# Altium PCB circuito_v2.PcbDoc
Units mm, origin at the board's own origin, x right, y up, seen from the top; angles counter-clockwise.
Board outline 77.47 x 60.58 mm, 2 copper layers (Top Layer, Bottom Layer); 47 components, 32 nets, 112 pads, 28 vias.
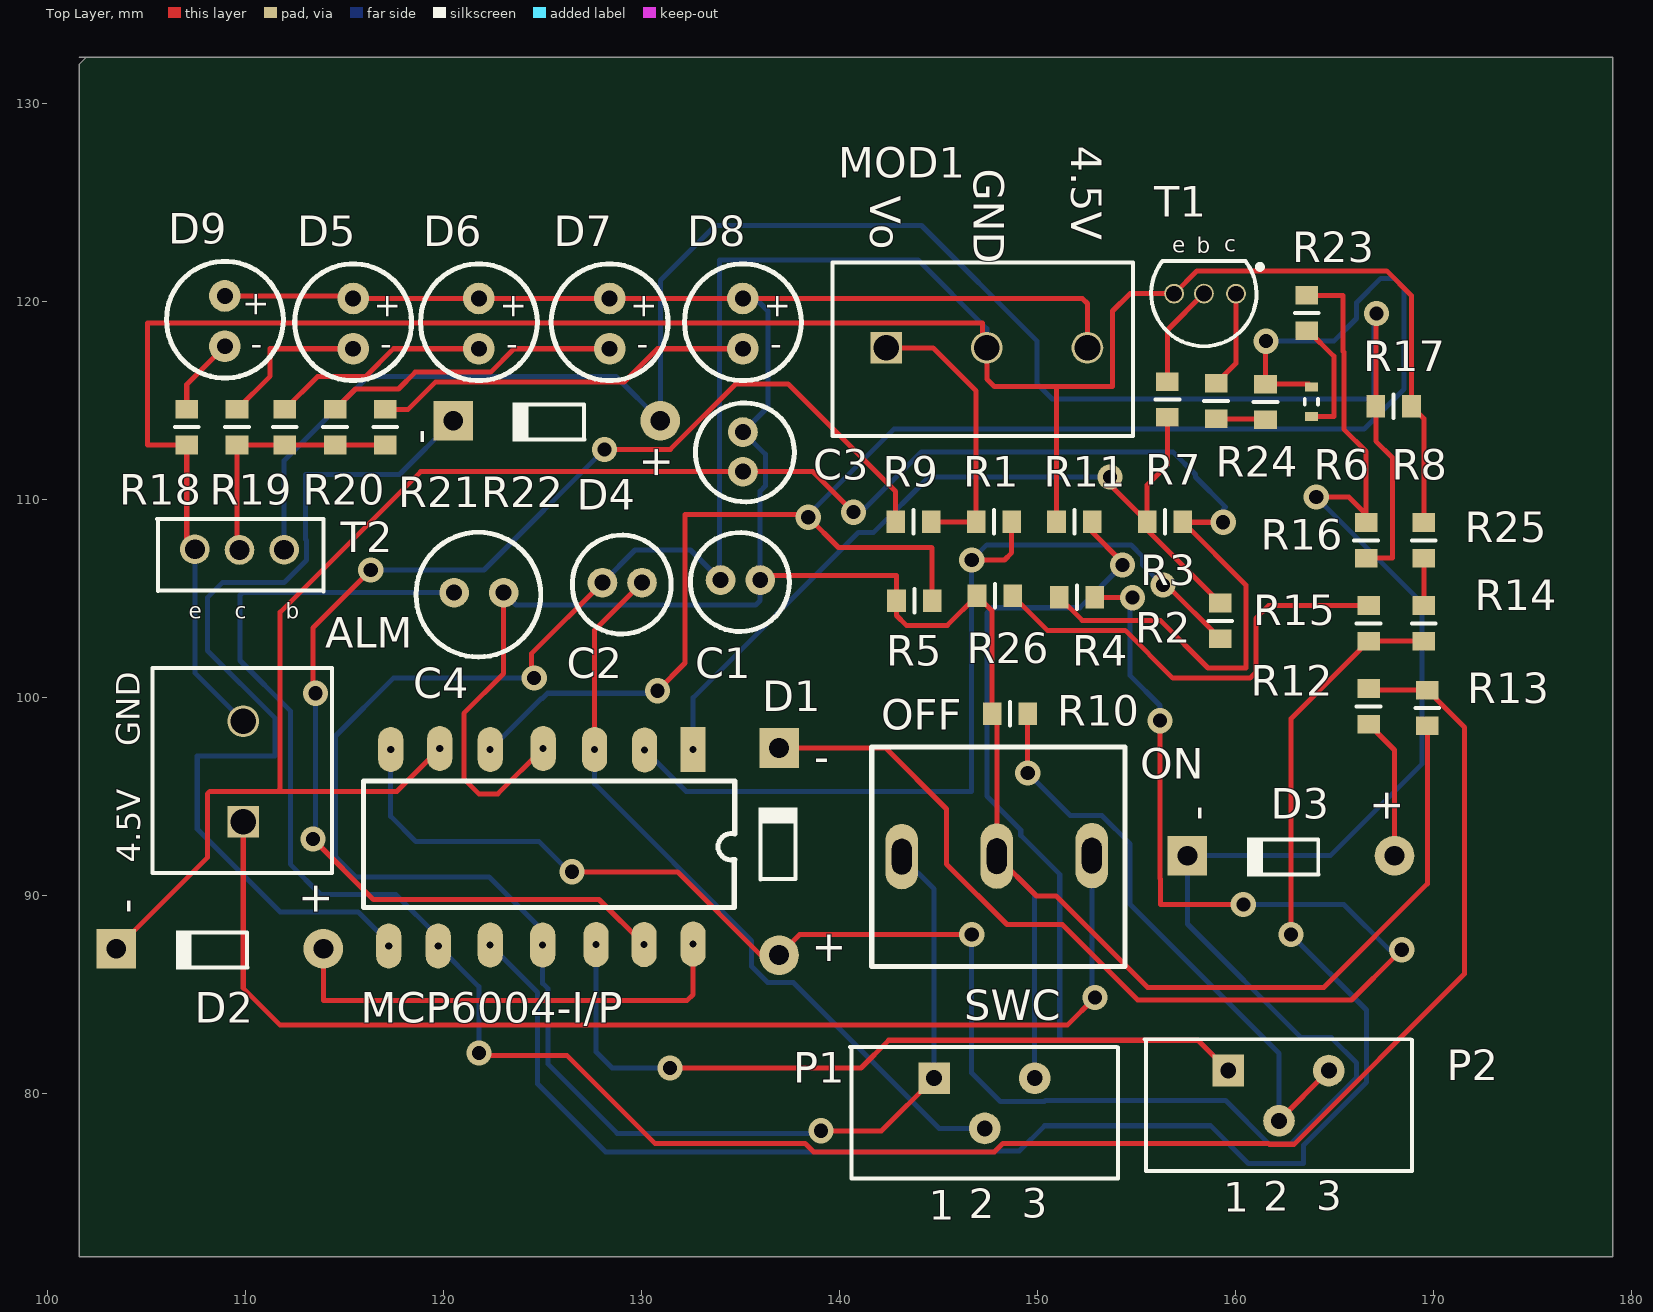
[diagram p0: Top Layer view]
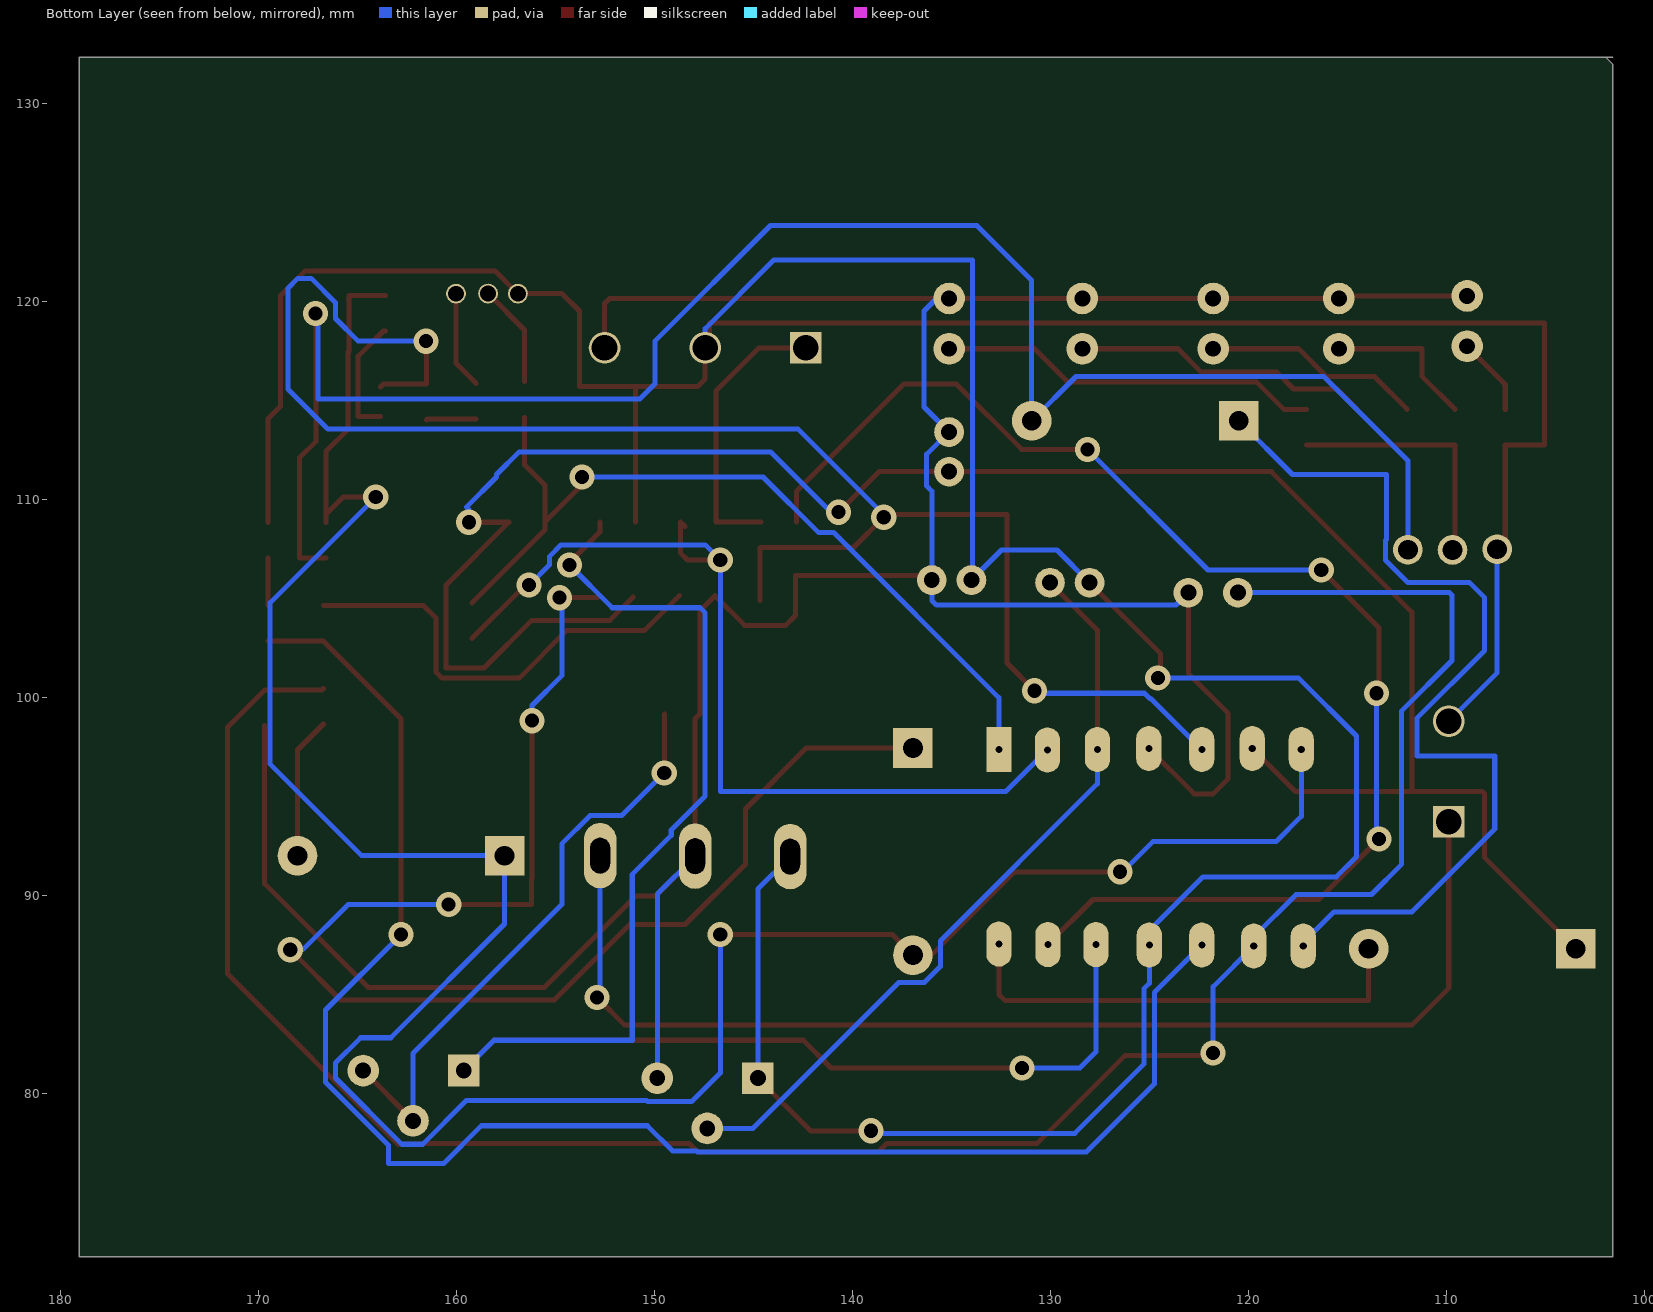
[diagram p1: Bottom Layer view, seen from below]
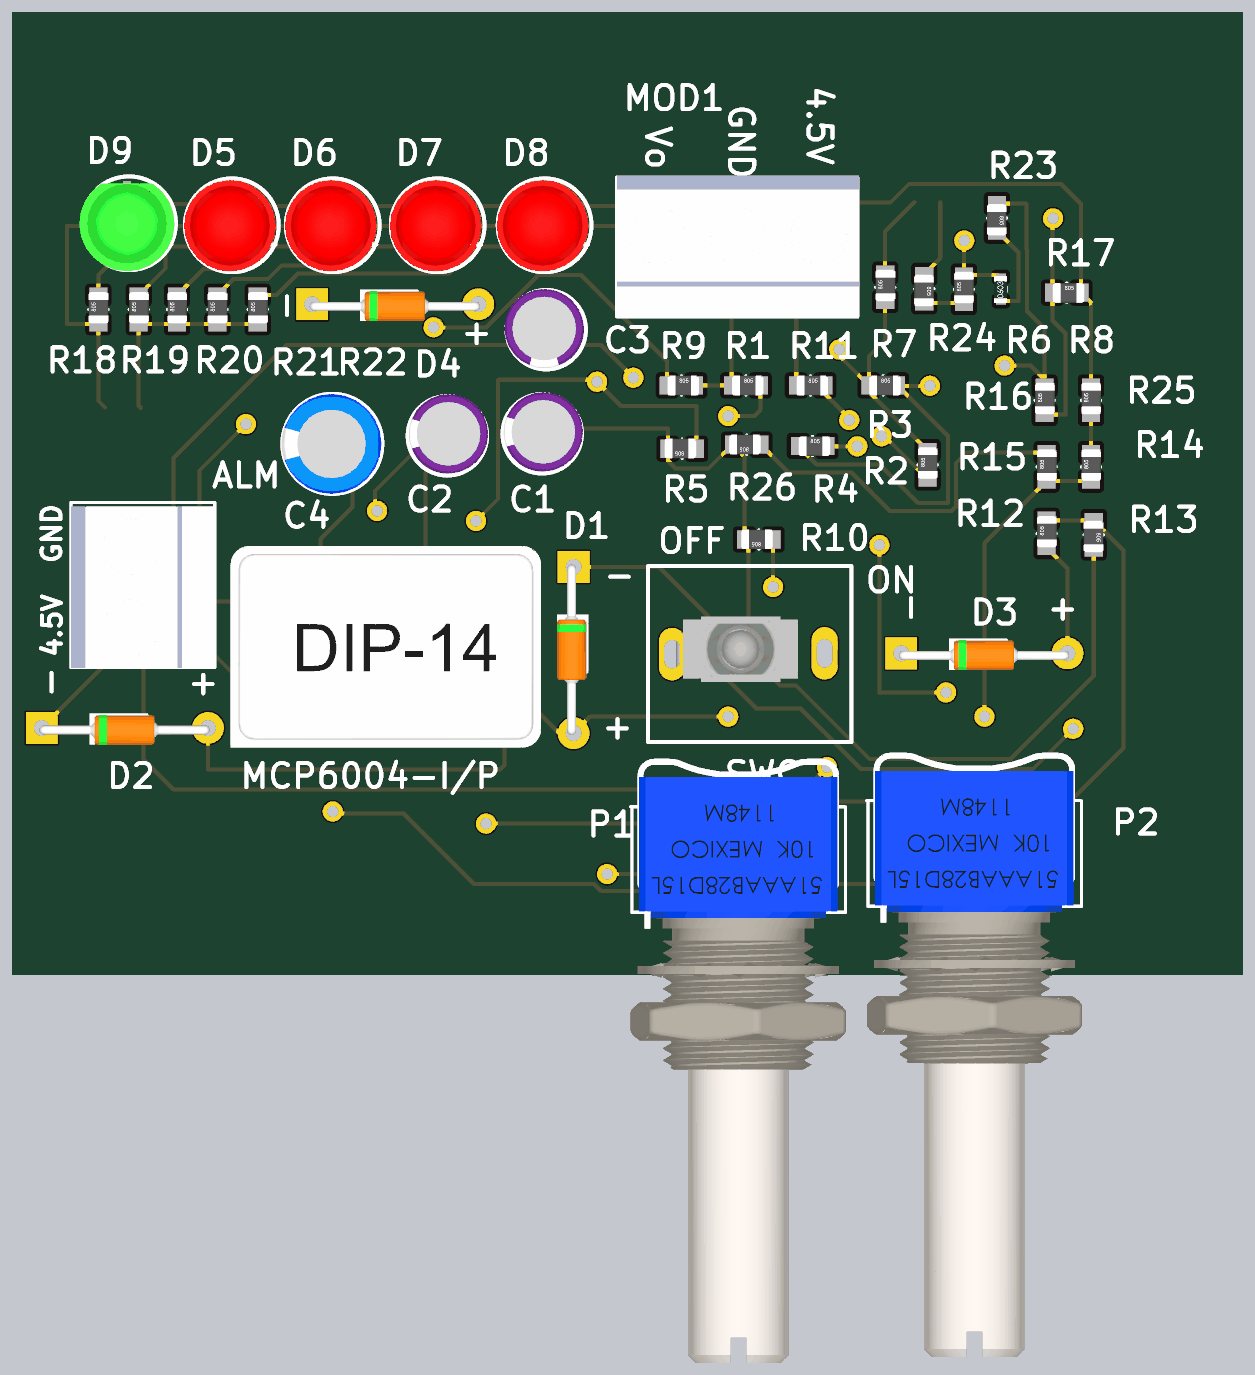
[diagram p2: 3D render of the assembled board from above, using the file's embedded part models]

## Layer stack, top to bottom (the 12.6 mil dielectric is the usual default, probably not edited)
Top Layer: signal copper 0.0356
Dielectric: dielectric 0.32, FR-4, Dk 4.8
Bottom Layer: signal copper 0.0356

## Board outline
101.6,132.334 179.07,132.334 179.07,71.755 101.6,71.755 101.6,131.953 101.981,132.334

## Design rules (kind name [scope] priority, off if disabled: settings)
Clearance Clearance_Vias_a_Mano [IsComponentBody vs IsVia] p1: gap=1.524
Clearance [All] p2: gap=0.254
MinimumSolderMaskSliver SilkscreenOverComponentPads [All] p2: minsoldermaskwidth=0.254
PolygonConnect [All] p1: connectstyle=Relief reliefconductorwidth=0.254 reliefentries=4 polygonreliefangle="90 Angle" airgapwidth=0.254
RoutingLayers RoutingLayers_1 [InNet('GND')] p1: top layer_v5=FALSE bottom layer_v5=FALSE
RoutingLayers [All] p2: top layer_v5=TRUE bottom layer_v5=TRUE
RoutingPriority RoutingPriority_GND [InNet('GND')] p1: routingpriority=0
RoutingPriority [All] p2: routingpriority=100
RoutingVias RoutingVias_A_Mano [All] p1: holewidth=0.889 width=2.032 viastyle="Through Hole" minholewidth=0.889 minwidth=1.778 maxholewidth=0.889 maxwidth=2.54
SolderMaskExpansion [All] p1: expansion=0.102
Width Width_Vcc [(InNet('VCC+') AND InNet('VCC-'))] p1: maxlimit=5.08 minlimit=1.778 preferedwidth=2.032
Width [All] p2: maxlimit=2.54 minlimit=0.254 preferedwidth=0.508
26 further rules are at their usual default settings.

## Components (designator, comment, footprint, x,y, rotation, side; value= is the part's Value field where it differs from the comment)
ALM "Header 2" ALM 126.492,107.188 r90 top
C1 "Cap" "Condensador 5mm" 135.001,105.918 r0 top
C2 "Cap" "Condensador 5mm" 129.032,105.791 r0 top
C3 "Cap" "Condensador 5mm" 135.128,112.395 r90 top
C4 "Cap" "Condensador 6.3mm" 121.793,105.283 r0 top
D1 "BAT85" BAT85 136.906,92.329 r0 top
D2 "Diode BAT18" BAT85 108.585,87.249 r90 top
D3 "Diode BAT18" BAT85 162.687,91.948 r90 top
D4 "Diode BAT18" BAT85 125.603,113.919 r90 top
D5 "LED" LED 115.443,120.142 r270 top
D6 "LED" LED 121.793,120.142 r270 top
D7 "LED" LED 128.397,120.142 r270 top
D8 "LED" LED 135.128,120.142 r270 top
D9 "LED" "LED verde" 108.966,120.269 r270 top
MCP6004-I/P "SW DIP-7" MCP6004 131.191,97.536 r270 top
MOD1 "Conector" Conector 178.562,108.839 r270 top
P1 "Res Tap" POTENCIOMETRO 147.32,80.772 r270 top
P2 "Res Tap" POTENCIOMETRO 162.179,81.153 r270 top
R1 "Res1" "SMD 0805" 140.843,110.998 r0 top
R2 "Res1" "SMD 0805" 157.099,96.901 r90 top
R3 "Res1" "SMD 0805" 149.479,110.998 r0 top
R4 "Res1" "SMD 0805" 145.034,107.188 r0 top
R5 "Res1" "SMD 0805" 150.749,102.743 r180 top
R6 "Res1" "SMD 0805" 159.385,107.95 r90 top
R7 "Res1" "SMD 0805" 154.432,108.077 r90 top
R8 "Res1" "SMD 0603" 163.83,114.935 r0 top
R9 "Res1" "SMD 0805" 136.779,110.998 r0 top
R10 "Res1" "SMD 0805" 155.575,97.028 r180 top
R11 "Res1" "SMD 0805" 144.907,110.998 r0 top
R12 "Res1" "SMD 0805" 164.592,92.583 r90 top
R13 "Res1" "SMD 0805" 171.831,106.426 r270 top
R14 "Res1" "SMD 0805" 167.386,96.774 r90 top
R15 "Res1" "SMD 0805" 164.592,96.774 r90 top
R16 "Res1" "SMD 0805" 164.465,100.965 r90 top
R17 "Res1" "SMD 0805" 161.036,116.84 r0 top
R18 "Res3" "SMD 0805" 104.902,106.68 r90 top
R19 "Res3" "SMD 0805" 107.442,106.68 r90 top
R20 "Res3" "SMD 0805" 109.855,106.68 r90 top
R21 "Res3" "SMD 0805" 112.395,106.68 r90 top
R22 "Res3" "SMD 0805" 114.935,106.68 r90 top
R23 "Res1" "SMD 0805" 165.735,126.365 r270 top
R24 "Resistencia" "SMD 0805" 161.163,121.92 r270 top
R25 "Resistencia" "SMD 0805" 167.386,100.965 r90 top
R26 "Resistencia" "SMD 0805" 154.813,102.997 r180 top
SWC "Conmutador" switch 145.161,91.313 r0 top
T1 "2N3904" "T1 BC550C" 148.082,179.959 r90 top
T2 "QNPN" "T2 BD139" 100.457,43.053 r270 top

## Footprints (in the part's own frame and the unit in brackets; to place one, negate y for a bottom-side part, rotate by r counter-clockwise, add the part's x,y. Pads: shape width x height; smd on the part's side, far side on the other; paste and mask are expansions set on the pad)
ALM [mm]
  rect 1.6x1.6 hole 1.3: 1(-13.48,16.6)
  round 1.6 hole 1.3: 2(-8.4,16.6)
  silkscreen extent -16.07,12.12 -5.7,21.17, body extent -16.1,12.18 -4.94,21.17, height 15.2
BAT85 [mm]
  round 2 hole 1: 1(0.049,-5.353)
  rect 2x2 hole 1: 2(0.049,5.107)
  silkscreen extent -1,-1.53 0.97,2.1, body extent -1.02,-5.46 0.88,5.26, height 1.95
"Condensador 5mm" [mm]
  round 1.5 hole 0.8: 1(-1,0) 2(1,0)
  silkscreen extent -2.52,-2.6 2.47,2.4, body extent -2.45,-2.47 2.55,2.52, height 11
"Condensador 6.3mm" [mm]
  round 1.5 hole 0.8: 1(-1.25,0) 2(1.25,0)
  silkscreen extent -3.17,-3.25 3.12,3.05, body extent -3.22,-3.25 3.08,3.05, height 11.5
Conector [mm]
  rect 1.6x1.6 hole 1.3: 1(-8.811,-36.193)
  round 1.6 hole 1.3: 2(-8.811,-31.113) 3(-8.811,-26.033)
  silkscreen extent -13.13,-38.9 -4.35,-23.72, body extent -13.25,-38.87 -4.25,-23.63, height 15.2
LED [mm]
  round 1.6 hole 0.8: 1(0,0) 2(2.54,0)
  silkscreen extent -1.75,-2.95 4.15,2.95, body extent -1.68,-3.03 4.12,2.77, height 17.5
"LED verde" [mm]
  round 1.6 hole 0.8: 1(0,0) 2(2.54,0)
  silkscreen extent -1.75,-2.95 4.15,2.95, body extent -1.47,-3.12 4.23,2.87, height 20.86
MCP6004 [mm]
  rect 2.286x1.27 hole 0.356: 1(0.175,1.425)
  oval 2.286x1.27 hole 0.356: 2(0.2,-1.025) 3(0.175,-3.55) 4(0.125,-6.15) 5(0.175,-8.825) 6(0.125,-11.375) 7(0.175,-13.85) 8(10.1,-13.95) 9(10.1,-11.45) 10(10.05,-8.825) 11(10.05,-6.175) 12(10.025,-3.475) 13(10.025,-1.05) 14(10,1.425)
  silkscreen extent 1.78,-15.22 8.15,3.52, body extent -1.22,-15.84 11.48,3.72, height 4.61
POTENCIOMETRO [mm]
  rect 1.6x1.6 hole 0.8: 1(0.008,-2.535)
  round 1.6 hole 0.8: 2(2.548,0.025) 3(0.008,2.545)
  silkscreen extent -1.58,-6.78 5.07,6.75, body extent -4.59,-6.77 33.45,6.77, height 14.1
"SMD 0603" [mm]
  rect 0.64x0.44 smd mask+0.26: 1(0.018,-0.76) 2(0.018,0.74)
  silkscreen extent -0.33,-0.15 0.35,0.13, body extent -0.4,-0.9 0.4,0.8, height 0.56
"SMD 0805" [mm]
  rect 0.94x1.14 smd mask+0.26: 1(6.062,-2.136) 2(7.862,-2.136)
  silkscreen extent 6.96,-2.74 6.96,-1.54, body extent 6.08,-2.77 8.08,-1.52, height 0.78
switch [mil]
  oval 65x130 hole 39.37 slot 70.87 at 90 deg: 1(-79,25) 2(109.96,26) 3(298.94,27)
  silkscreen extent -139,-193 365,243, body extent -69,-61 250,136, height 720
"T1 BC550C" [mm]
  round 1 hole 0.8: 1(-59.575,-11.95) 2(-59.571,-10.328) 3(-59.575,-8.825)
  silkscreen extent -62.23,-13.28 -57.92,-7.67, body extent -61.73,-12.63 -58.1,-7.87, height 4.92
"T2 BD139" [mm]
  round 1.5 hole 1: 1(-64.425,6.992) 2(-64.389,9.246) 3(-64.4,11.5)
  silkscreen extent -65.95,5.07 -62.3,13.5, body extent -65.4,5.4 -62.7,13.2, height 13.6

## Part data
ALM: "Header, 2-Pin"
C1 C2 C3 C4: "Capacitor"
D1: library part "Diode BAT18", "Low-Loss RF Switching Diode"
D2 D3 D4: "Low-Loss RF Switching Diode"
D5 D6 D7 D8 D9: library part LED2, "Typical RED, GREEN, YELLOW, AMBER GaAs LED"
MCP6004-I/P: "DIP Switch, 7 Position, SPST"
MOD1: library part "Header 3", "Header, 3-Pin"
P1 P2: "Tapped Resistor"
R1 R2 R3 R4 R5 R6 R7 R8 R9 R10 R11 R12 R13 R14 R15 R16 R17 R18 R19 R20 R21 R22 R23 R24 R25 R26: "Resistor"
T1: "NPN General Purpose Amplifier"
T2: "NPN Bipolar Transistor"

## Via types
v1: diameter 1.27, hole 0.711, Top Layer to Bottom Layer, 28 vias

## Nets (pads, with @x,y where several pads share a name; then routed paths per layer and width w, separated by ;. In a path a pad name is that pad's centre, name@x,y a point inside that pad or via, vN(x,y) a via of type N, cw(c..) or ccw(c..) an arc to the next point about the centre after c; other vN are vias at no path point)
GND: ALM.2 C1.1 C2.1 MCP6004-I/P.11 MOD1.2 P1.1 R11.1 R17.2 R18.1 R25.2 SWC.1 T1.3 T2.1 | length 228.8
  Top Layer w0.254: T2.1 107.038,107.889 R18.1 105.063,112.742 105.063,118.906 105.067,118.91 147.231,118.91 147.231,117.868 MOD1.2 147.449,116.076 147.828,115.697 150.876,115.697 ; v1@124.46,101.346 124.46,102.219 C2.1 ; v1(139.065,78.105) 142.126,78.105 P1.1 ; R11.1 150.969,115.604 150.876,115.697 ; R25.2 169.522,114.08 R17.2 168.898,120.281 167.64,121.539 158.062,121.539 T1.3 154.674,120.384 153.797,119.507 153.797,115.697 150.876,115.697
  Bottom Layer w0.254: T2.1 107.449,101.231 ALM.2 ; v1(124.587,100.965) 117.475,100.965 114.554,98.044 114.554,91.948 115.57,90.932 122.301,90.932 125.016,88.217 MCP6004-I/P.11 125.016,85.554 125.273,85.297 125.273,81.483 128.778,77.978 v1@138.811,77.978 ; C2.1 129.683,107.442 132.477,107.442 C1.1@133.947,105.972 ; C1.1 C1.1@133.947,105.972 ; SWC.1 144.785,90.317 P1.1 ; MOD1.2 147.449,118.616 143.98,122.085 133.947,122.085 C1.1@133.947,105.972
NetALM_1: ALM.1 SWC.3 | length 60
  Top Layer w0.254: ALM.1 109.892,85.307 111.76,83.439 151.511,83.439 v1(152.908,84.836)
  Bottom Layer w0.254: SWC.3 152.754,84.99 v1(152.908,84.836)
NetD1_3: D1.2 R4.2 | length 70
  Top Layer w0.254: D1.2 142.34,97.436 145.415,94.361 145.415,91.567 148.463,88.519 151.257,88.519 155.067,84.709 165.862,84.709 v1@168.148,86.995 ; R4.2 152.919,105.029 v1(154.813,105.029) ; v1(156.199,98.817) 156.199,90.839 156.21,90.828 156.21,89.535 v1(160.401,89.535)
  Bottom Layer w0.254: v1@154.686,104.775 154.686,101.092 156.199,99.579 v1(156.199,98.817) ; v1(160.401,89.535) 165.481,89.535 167.767,87.249 v1(168.402,87.249)
NetD2_1: D2.1 MCP6004-I/P.14 | length 24
  Top Layer w0.254: D2.1 113.938,84.69 132.315,84.69 132.616,84.991 MCP6004-I/P.14
NetD3_1: D3.1 R12.1 | length 7.2
  Top Layer w0.254: R12.1 168.04,97.333 D3.1
NetD4_1: D4.1 R16.1 R17.1 T2.3 | length 93.8
  Top Layer w0.254: R16.1 167.928,107.027 167.928,112.107 167.098,112.937 R17.1 167.098,119.346 v1(167.132,119.38)
  Bottom Layer w0.254: T2.3 111.957,111.957 116.205,116.205 128.719,116.205 D4.1 130.956,121.05 133.731,123.825 144.145,123.825 149.987,117.983 149.987,115.824 150.749,115.062 167.005,115.062 167.005,119.253 v1(167.132,119.38)
NetD5_2: D5.2 R19.2 | length 7.9
  Top Layer w0.254: R19.2 111.252,116.216 111.252,117.602 D5.2
NetD6_2: D6.2 R20.2 | length 11.1
  Top Layer w0.254: R20.2 113.654,116.205 116.078,116.205 117.475,117.602 D6.2
NetD7_2: D7.2 R21.2 | length 15.1
  Top Layer w0.254: R21.2 115.559,115.57 117.729,115.57 118.58,116.421 122.39,116.421 123.571,117.602 D7.2
NetD8_2: D8.2 R22.2 | length 19.3
  Top Layer w0.254: R22.2 118.225,114.542 119.596,115.913 129.121,115.913 130.81,117.602 D8.2
NetD9_2: D9.2 R18.2 | length 4
  Top Layer w0.254: R18.2 107.038,115.801 D9.2
NetMOD1_1: MOD1.1 R1.1 R9.2 | length 14.3
  Top Layer w0.254: MOD1.1 144.732,117.65 146.905,115.477 R1.1 R9.2
NetP2_1: P2.2 P2.3 R10.1 | length 30.4
  Top Layer w0.254: v1@149.479,96.139 v1(149.513,96.173) R10.1 ; P2.2 162.204,78.625 P2.3
  Bottom Layer w0.254: v1(149.513,96.173) 151.655,94.031 153.254,94.031 154.686,92.599 154.686,89.535 162.204,82.017 P2.2
NetR6_1: R6.1 R24.2 | length 2.5
  Top Layer w0.254: R24.2 161.475,114.058 R6.1
NetR7_2: R7.2 T1.2 | length 5.2
  Top Layer w0.254: R7.2 156.568,118.546 T1.2
NetR8_1: R8.1 R23.2 | length 6.1
  Top Layer w0.254: R23.2 163.691,118.503 164.971,117.223 164.971,114.175 R8.1
NetR14_2: R14.2 R25.1 | length 2.4
  Top Layer w0.254: R14.2 R25.1
NetR15_2: R15.2 R26.1 | length 22.8
  Top Layer w0.254: R26.1 150.506,103.378 154.432,103.378 156.845,100.965 160.738,100.965 161.036,101.263 161.036,103.989 161.683,104.636 R15.2
NetR19_1: R19.1 R20.1 R21.1 R22.1 T2.2 | length 12.8
  Top Layer w0.254: T2.2 109.578,107.567 R19.1 R20.1 R21.1 R22.1
NetR24_1: R24.1 T1.1 | length 4.9
  Top Layer w0.254: R24.1 160.032,116.863 T1.1
VA+: C2.2 MCP6004-I/P.3 P1.2 | length 38.8
  Top Layer w0.254: MCP6004-I/P.3 127.641,103.4 C2.2
  Bottom Layer w0.254: MCP6004-I/P.3 127.641,95.625 135.574,87.692 135.574,86.404 136.383,85.595 137.671,85.595 145.042,78.224 P1.2
VA-: MCP6004-I/P.2 R1.2 R2.1 | length 48.2
  Top Layer w0.254: v1(146.685,106.934) 148.336,106.934 148.705,107.303 R1.2 R1.2@148.463,108.62 ; v1(156.337,105.664) 156.534,105.664 R2.1
  Bottom Layer w0.254: MCP6004-I/P.2 132.252,95.25 146.685,95.25 v1(146.685,106.934) 147.447,107.696 154.726,107.696 155.321,107.101 155.321,106.68 v1(156.337,105.664)
VB+: MCP6004-I/P.5 R5.1 R6.2 R8.2 | length 85.6
  Top Layer w0.254: v1(130.81,100.33) 132.207,101.727 132.207,109.22 138.303,109.22 v1(138.43,109.093) 139.954,107.569 144.653,107.569 144.687,107.535 R5.1 ; v1@161.521,117.579 R6.2 163.711,115.812 R8.2
  Bottom Layer w0.254: MCP6004-I/P.5 124.954,99.949 125.008,99.949 125.262,100.203 v1@130.683,100.203 ; v1@138.557,109.347 142.748,113.538 166.497,113.538 168.529,115.57 168.529,120.65 168.021,121.158 167.346,121.158 166.116,119.928 166.116,119.126 164.973,117.983 v1(161.544,117.983)
VB-: C3.1 D2.2 MCP6004-I/P.6 R3.2 R4.1 | length 108.1
  Top Layer w0.254: D2.2 108.077,91.897 108.077,95.123 108.204,95.25 111.633,95.25 ; MCP6004-I/P.6 117.655,95.25 111.633,95.25 ; v1@140.843,109.347 v1(140.716,109.347) 138.668,111.395 C3.1 118.856,111.395 111.76,104.299 111.76,95.377 111.633,95.25 ; R4.1 152.262,103.886 156.21,103.886 158.623,101.473 160.528,101.473 160.528,105.675 157.364,108.839 v1(159.385,108.839)
  Bottom Layer w0.254: v1(140.716,109.347) 141.097,109.347 144.145,112.395 156.845,112.395 157.988,111.252 157.988,111.125 159.512,109.601 159.385,109.474 v1(159.385,108.839)
VC+: MCP6004-I/P.10 R14.1 R15.1 | length 83.3
  Top Layer w0.254: v1(162.814,88.011) 162.814,98.922 R15.1 R14.1
  Bottom Layer w0.254: MCP6004-I/P.10 124.765,85.087 124.765,80.467 128.189,77.043 147.834,77.043 147.88,77.089 149.098,77.089 150.368,78.359 158.75,78.359 160.655,76.454 163.449,76.454 163.449,77.387 166.624,80.562 166.624,84.201 v1(162.814,88.011) v1@162.687,88.138
VC-: C4.1 MCP6004-I/P.9 R12.2 R13.1 | length 114.9
  Top Layer w0.254: v1(121.793,82.042) 121.92,81.915 126.238,81.915 130.683,77.47 138.263,77.47 138.69,77.043 147.834,77.043 148.261,77.47 161.669,77.47 161.715,77.424 162.97,77.424 171.577,86.031 171.577,98.482 R13.1 166.809,100.364 R12.2
  Bottom Layer w0.254: C4.1 109.855,105.283 109.728,105.156 109.728,101.854 112.268,99.314 112.268,91.567 113.792,90.043 117.602,90.043 119.741,87.904 MCP6004-I/P.9 121.793,85.384 v1(121.793,82.042)
"VCC (4.5 V)": C1.2 C3.2 C4.2 D5.1 D6.1 D7.1 D8.1 D9.1 MCP6004-I/P.4 MOD1.3 P1.3 R5.2 R10.2 R13.2 R26.2 SWC.2 | length 166
  Top Layer w0.254: D9.1 D5.1@115.316,120.269 ; D5.1 D6.1 D7.1 D8.1 152.273,120.142 152.529,119.886 MOD1.3 ; C4.2 123.043,101.199 121.031,99.187 121.031,95.885 121.793,95.123 122.753,95.123 MCP6004-I/P.4 ; C1.2 136.232,106.149 142.887,106.149 R5.2 142.887,104.128 143.383,103.632 145.45,103.632 R26.2 147.713,104.371 R10.2 147.954,98.923 SWC.2 149.961,89.967 150.952,89.967 155.575,85.344 164.465,85.344 169.695,90.574 R13.2
  Bottom Layer w0.254: C4.2 123.666,104.66 135.775,104.66 136.001,104.886 C1.2 136.001,110.411 136.259,110.669 136.259,112.28 135.144,113.395 C3.2 136.398,114.665 136.398,119.507 135.763,120.142 D8.1 ; SWC.2 149.865,90.062 P1.3
VD+: MCP6004-I/P.12 P2.1 R11.2 | length 81.5
  Top Layer w0.254: v1(131.445,81.28) 141.097,81.28 142.494,82.677 158.112,82.677 P2.1 ; R11.2 152.769,108.343 v1@154.178,106.934
  Bottom Layer w0.254: MCP6004-I/P.12 127.716,82.088 128.524,81.28 v1(131.445,81.28) ; v1(154.305,106.68) 152.146,104.521 147.701,104.521 147.447,104.267 147.447,95.012 149.16,93.299 149.16,93.029 151.13,91.059 151.13,82.677 158.112,82.677 P2.1
VD-: MCP6004-I/P.13 R9.1 | length 67.5
  Top Layer w0.254: v1(113.411,92.837) 116.459,89.789 127.863,89.789 MCP6004-I/P.13 ; v1@113.411,100.457 113.411,103.505 v1(116.332,106.426) ; v1(128.143,112.522) 131.463,112.522 134.765,115.824 137.414,115.824 142.841,110.397 R9.1
  Bottom Layer w0.254: v1(113.411,92.837) 113.538,92.964 v1(113.538,100.203) ; v1@116.586,106.426 122.047,106.426 v1(128.143,112.522)
VOUTA: MCP6004-I/P.1 R2.2 R3.1 R7.1 | length 42.7
  Top Layer w0.254: v1(153.67,111.125) 153.67,110.733 R3.1 ; R7.1 156.568,111.737 155.541,110.71 R3.1 ; R2.2 155.541,108.457 R3.1
  Bottom Layer w0.254: MCP6004-I/P.1 132.616,99.977 140.97,108.331 141.732,108.331 144.526,111.125 v1(153.67,111.125)
VOUTB: D1.1 D3.2 MCP6004-I/P.7 R16.2 R23.1 | length 126.7
  Top Layer w0.254: v1(126.492,91.186) 131.826,91.186 136.036,86.976 D1.1 137.99,88.011 v1(146.685,88.011) ; R23.1 165.447,120.303 165.447,117.465 165.479,117.433 165.479,113.54 166.601,112.418 R16.2@166.601,109.243 ; v1(164.084,110.109) 165.735,110.109 R16.2@166.601,109.243 ; R16.2 R16.2@166.601,109.243
  Bottom Layer w0.254: MCP6004-I/P.7 117.341,93.987 118.618,92.71 124.841,92.71 v1@126.111,91.44 ; v1(146.685,88.011) 146.685,81.026 148.128,79.583 150.354,79.583 150.4,79.629 159.51,79.629 161.715,77.424 162.768,77.424 166.116,80.772 166.116,81.534 164.846,82.804 163.322,82.804 157.58,88.546 D3.2 164.797,91.997 169.418,96.618 169.418,104.775 v1(164.084,110.109)
VOUTC: D4.2 MCP6004-I/P.8 | length 48
  Bottom Layer w0.254: MCP6004-I/P.8 117.241,87.61 115.697,89.154 111.76,89.154 107.569,93.345 107.569,97.028 111.506,97.028 111.506,98.933 108.077,102.362 108.077,105.029 108.839,105.791 111.952,105.791 113.088,106.927 113.088,107.921 113.03,107.979 113.03,111.252 117.78,111.252 D4.2

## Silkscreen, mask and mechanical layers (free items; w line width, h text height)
Mechanical 16:
  drawing of 1874 lines, arcs and shapes, not listed
  text "1" at 36.246,189.611 h1.78
  text "2" at 108.89,189.611 h1.78
  text "3" at 182.042,189.611 h1.78
  text "4" at 254.94,189.611 h1.78
  text "A" at 1.905,166.599 h1.78
  text "A" at 288.925,166.599 h1.78
  text "B" at 1.905,118.542 h1.78
  text "B" at 288.925,118.542 h1.78
  text "C" at 293.139,70.57 h1.78
  text "C" at 1.905,70.028 h1.78
  text "ENGINEER:" at 173.99,33.02 h1.14
  text "TITLE:" at 212.09,33.02 h1.14
  text "PCB DESIGNER:" at 173.99,25.527 h1.14
  text "D" at 1.905,22.022 h1.78
  text "D" at 288.925,22.022 h1.78
  text "DATE:" at 173.99,17.78 h1.14
  text "PART NO.:" at 212.09,17.78 h1.14
  text "REV:" at 265.43,17.78 h1.14
  text "Altium Limited" at 140.97,15.24 h1.78
  text ".PRINT_DATE" at 175.26,14.732 h1.78
  text "12a Rodborough Rd" at 140.97,12.7 h1.78
  text "Frenchs Forest" at 140.97,10.16 h1.78
  text "FILE NAME:" at 173.99,10.16 h1.14
  text "DWG NO:" at 212.09,10.16 h1.14
  text "SCALE:" at 265.43,10.16 h1.14
  text "NSW 2086" at 140.97,7.62 h1.78
  text ".PCB_FILE_NAME_NO_PATH" at 175.26,7.112 h1.78
  text "1" at 36.246,1.651 h1.78
  text "2" at 108.89,1.651 h1.78
  text "3" at 182.042,1.651 h1.78
  text "4" at 254.94,1.651 h1.78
